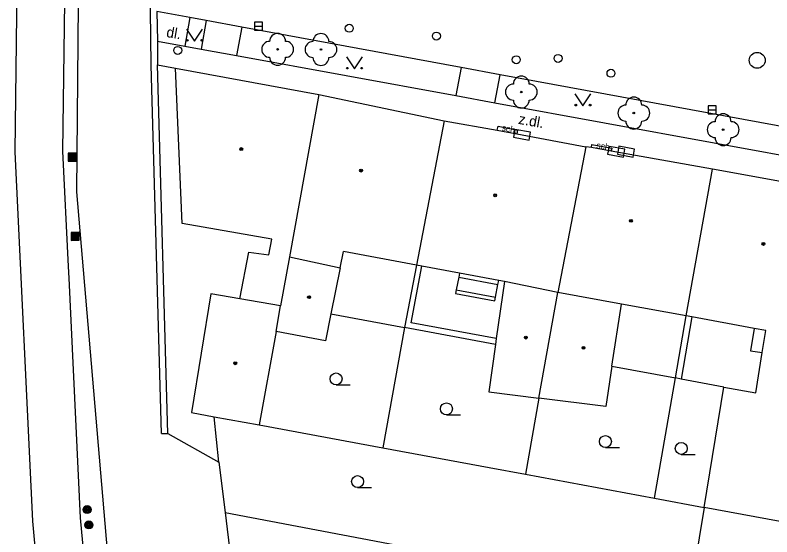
# Model space of a CAD drawing. Extents: x -596229 to -595156, y -1161237 to -1159376.
# Drawn here: x -596138.97 to -596091.46, y -1160439.45 to -1160406.71 of the extents above; entities that cross this region are included whole.
import ezdxf

# ---------------------------------------------------------------- set-up
doc = ezdxf.new("R2010")
doc.units = 0
for name, color, linetype in [('DOP - budovy nerozlisene - VP', 7, 'Continuous'), ('DOP - kresba z DSPS bez souradnic', 7, 'Continuous'), ('DOP - rozhrani ploch obecne', 7, 'Continuous'), ('Level 22', 7, 'Continuous'), ('Level 24', 7, 'Continuous'), ('Level 25', 7, 'Continuous'), ('Level 27', 7, 'Continuous'), ('Level 28', 7, 'Continuous'), ('Level 36', 7, 'Continuous'), ('Level 39', 7, 'Continuous'), ('TM - budovy zdene_ betonove - VP', 7, 'Continuous'), ('TM - CD - osa koleji', 7, 'Continuous'), ('TM - chodniky - VP', 7, 'Continuous'), ('TM - horni hrana svahu', 7, 'Continuous'), ('TM - komunikace - VP', 7, 'Continuous'), ('TM - letecke snimky - pomocna linie', 7, 'Continuous'), ('TM - plot drateny_ kovovy - VP', 7, 'Continuous'), ('TM - plot nerozliseny - VP', 7, 'Continuous'), ('TM - popis povrchu', 7, 'Continuous'), ('TM - poznamka', 7, 'Continuous'), ('TM - rozhrani mezi zpev. plochami mezi sebou - VP', 7, 'Continuous'), ('TM - rozhrani ploch obecne - VP', 7, 'Continuous'), ('TM - schody - VP', 7, 'Continuous'), ('TM - zed operna - VP', 7, 'Continuous')]:
    doc.layers.add(name, color=color, linetype=linetype)

msp = doc.modelspace()

# ---------------------------------------------------------------- linework, layer by layer
at = {"layer": 'DOP - budovy nerozlisene - VP'}
for points in [[(-596126.68, -1160424.21), (-596127.89, -1160431.65)], [(-596124.86, -1160424.52), (-596126.68, -1160424.21)], [(-596122.59, -1160426.57), (-596123.65, -1160432.43)], [(-596127.89, -1160431.65), (-596126.48, -1160431.91)], [(-596126.48, -1160431.91), (-596123.65, -1160432.43)]]:
    msp.add_lwpolyline(points, dxfattribs=at)
at = {"layer": 'DOP - kresba z DSPS bez souradnic'}
for points in [[(-596114.11, -1160426.03), (-596113.43, -1160422.46)], [(-596096.49, -1160425.65), (-596097.15, -1160429.55)], [(-596108.76, -1160427.01), (-596114.11, -1160426.03)]]:
    msp.add_lwpolyline(points, dxfattribs=at)
at = {"layer": 'DOP - rozhrani ploch obecne'}
for points in [[(-596113.77, -1160422.4), (-596114.52, -1160426.31)], [(-596119.15, -1160425.45), (-596114.52, -1160426.31)], [(-596097.5, -1160429.48), (-596096.84, -1160425.58)], [(-596114.52, -1160426.31), (-596115.88, -1160433.87)], [(-596108.81, -1160427.37), (-596114.52, -1160426.31)], [(-596101.5, -1160428.74), (-596097.5, -1160429.48)], [(-596098.83, -1160437.02), (-596097.5, -1160429.48)], [(-596097.15, -1160429.55), (-596097.5, -1160429.48)], [(-596094.47, -1160430.05), (-596097.15, -1160429.55)], [(-596106.1, -1160430.75), (-596106.93, -1160435.52)], [(-596126.19, -1160434.76), (-596126.48, -1160431.91)], [(-596123.65, -1160432.43), (-596115.88, -1160433.87)], [(-596115.88, -1160433.87), (-596109.2, -1160435.1)], [(-596109.2, -1160435.1), (-596106.93, -1160435.52)], [(-596106.93, -1160435.52), (-596098.83, -1160437.02)], [(-596098.83, -1160437.02), (-596095.71, -1160437.6)], [(-596125.79, -1160437.93), (-596096.67, -1160443.44)]]:
    msp.add_lwpolyline(points, dxfattribs=at)
at = {"layer": 'Level 22'}
for centre in [(-596122.49, -1160408.86), (-596119.77, -1160408.87), (-596107.19, -1160411.54), (-596100.13, -1160412.86), (-596094.52, -1160413.9)]:
    msp.add_circle(centre, 0.05, dxfattribs=at)
for centre, start, end in [((-596122.49, -1160408.36), 0, 180), ((-596119.77, -1160408.37), 0, 180), ((-596122.99, -1160408.86), 90, 270), ((-596121.99, -1160408.86), 270, 90), ((-596120.27, -1160408.87), 90, 270), ((-596119.27, -1160408.87), 270, 90), ((-596122.49, -1160409.36), 180, 0), ((-596119.77, -1160409.37), 180, 0), ((-596107.19, -1160411.04), 0, 180), ((-596107.69, -1160411.54), 90, 270), ((-596106.69, -1160411.54), 270, 90), ((-596107.19, -1160412.04), 180, 0), ((-596100.13, -1160412.36), 0, 180), ((-596100.63, -1160412.86), 90, 270), ((-596099.63, -1160412.86), 270, 90), ((-596094.52, -1160413.4), 0, 180), ((-596100.13, -1160413.36), 180, 0), ((-596095.02, -1160413.9), 90, 270), ((-596094.02, -1160413.9), 270, 90), ((-596094.52, -1160414.4), 180, 0)]:
    msp.add_arc(centre, 0.5, start, end, dxfattribs=at)
at = {"layer": 'Level 24'}
for points in [[(-596106.606, -1160414.065), (-596107.589, -1160413.882), (-596107.68, -1160414.374), (-596106.697, -1160414.557)], [(-596100.697, -1160415.132), (-596101.681, -1160414.955), (-596101.769, -1160415.447), (-596100.785, -1160415.624)], [(-596100.076, -1160415.124), (-596101.06, -1160414.944), (-596101.15, -1160415.435), (-596100.166, -1160415.616)]]:
    msp.add_lwpolyline(points, close=True, dxfattribs=at)
at = {"layer": 'Level 25'}
for points in [[(-596135.635, -1160415.885), (-596135.135, -1160415.875), (-596135.145, -1160415.375), (-596135.645, -1160415.385)], [(-596135.586, -1160415.834), (-596135.186, -1160415.826), (-596135.194, -1160415.426), (-596135.594, -1160415.434)], [(-596135.537, -1160415.783), (-596135.237, -1160415.777), (-596135.243, -1160415.477), (-596135.543, -1160415.483)], [(-596135.488, -1160415.732), (-596135.288, -1160415.728), (-596135.292, -1160415.528), (-596135.492, -1160415.532)], [(-596135.439, -1160415.681), (-596135.339, -1160415.679), (-596135.341, -1160415.579), (-596135.441, -1160415.581)], [(-596135.445, -1160420.845), (-596134.945, -1160420.835), (-596134.955, -1160420.335), (-596135.455, -1160420.345)], [(-596135.396, -1160420.794), (-596134.996, -1160420.786), (-596135.004, -1160420.386), (-596135.404, -1160420.394)], [(-596135.347, -1160420.743), (-596135.047, -1160420.737), (-596135.053, -1160420.437), (-596135.353, -1160420.443)], [(-596135.298, -1160420.692), (-596135.098, -1160420.688), (-596135.102, -1160420.488), (-596135.302, -1160420.492)], [(-596135.249, -1160420.641), (-596135.149, -1160420.639), (-596135.151, -1160420.539), (-596135.251, -1160420.541)]]:
    msp.add_lwpolyline(points, close=True, dxfattribs=at)
for centre, radius in [((-596134.45, -1160437.74), 0.25), ((-596134.45, -1160437.74), 0.2), ((-596134.45, -1160437.74), 0.15), ((-596134.45, -1160437.74), 0.1), ((-596134.45, -1160437.74), 0.05), ((-596134.34, -1160438.7), 0.25), ((-596134.34, -1160438.7), 0.2), ((-596134.34, -1160438.7), 0.15), ((-596134.34, -1160438.7), 0.1), ((-596134.34, -1160438.7), 0.05)]:
    msp.add_circle(centre, radius, dxfattribs=at)
at = {"layer": 'Level 27'}
for p, q in [((-596123.94, -1160407.4), (-596123.44, -1160407.4)), ((-596095.46, -1160412.66), (-596094.96, -1160412.66))]:
    msp.add_line(p, q, dxfattribs=at)
for points in [[(-596123.94, -1160407.65), (-596123.44, -1160407.65), (-596123.44, -1160407.15), (-596123.94, -1160407.15)], [(-596095.46, -1160412.91), (-596094.96, -1160412.91), (-596094.96, -1160412.41), (-596095.46, -1160412.41)]]:
    msp.add_lwpolyline(points, close=True, dxfattribs=at)
msp.add_circle((-596092.38, -1160409.55), 0.5, dxfattribs=at)
at = {"layer": 'Level 28'}
for centre in [(-596117.99, -1160407.54), (-596112.52, -1160408.03), (-596128.76, -1160408.93), (-596107.51, -1160409.51), (-596104.88, -1160409.43), (-596101.56, -1160410.36)]:
    msp.add_circle(centre, 0.25, dxfattribs=at)
at = {"layer": 'Level 36'}
for p, q in [((-596118.82, -1160429.915), (-596117.945, -1160429.915)), ((-596111.89, -1160431.795), (-596111.015, -1160431.795)), ((-596101.91, -1160433.845), (-596101.035, -1160433.845)), ((-596097.15, -1160434.275), (-596096.275, -1160434.275)), ((-596117.47, -1160436.355), (-596116.595, -1160436.355))]:
    msp.add_line(p, q, dxfattribs=at)
for points in [[(-596128.21, -1160407.59), (-596127.71, -1160408.34), (-596127.21, -1160407.59)], [(-596118.16, -1160409.34), (-596117.66, -1160410.09), (-596117.16, -1160409.34)], [(-596103.82, -1160411.66), (-596103.32, -1160412.41), (-596102.82, -1160411.66)]]:
    msp.add_lwpolyline(points, dxfattribs=at)
for centre, radius in [((-596128.16, -1160408.29), 0.05), ((-596127.261, -1160408.29), 0.05), ((-596118.11, -1160410.04), 0.05), ((-596117.211, -1160410.04), 0.05), ((-596103.77, -1160412.36), 0.05), ((-596102.871, -1160412.36), 0.05), ((-596118.82, -1160429.54), 0.375), ((-596111.89, -1160431.42), 0.375), ((-596101.91, -1160433.47), 0.375), ((-596097.15, -1160433.9), 0.375), ((-596117.47, -1160435.98), 0.375)]:
    msp.add_circle(centre, radius, dxfattribs=at)
at = {"layer": 'Level 39'}
for centre, radius in [((-596124.77, -1160415.12), 0.09), ((-596124.77, -1160415.12), 0.0398), ((-596117.25, -1160416.47), 0.09), ((-596117.25, -1160416.47), 0.0398), ((-596108.83, -1160418.02), 0.09), ((-596108.83, -1160418.02), 0.0398), ((-596100.31, -1160419.62), 0.09), ((-596100.31, -1160419.62), 0.0398), ((-596091.99, -1160421.07), 0.09), ((-596091.99, -1160421.07), 0.0398), ((-596120.52, -1160424.41), 0.09), ((-596120.52, -1160424.41), 0.0398), ((-596106.91, -1160426.95), 0.09), ((-596106.91, -1160426.95), 0.0398), ((-596103.29, -1160427.59), 0.09), ((-596103.29, -1160427.59), 0.0398), ((-596125.15, -1160428.56), 0.09), ((-596125.15, -1160428.56), 0.0398)]:
    msp.add_circle(centre, radius, dxfattribs=at)
at = {"layer": 'TM - budovy zdene_ betonove - VP'}
for points in [[(-596128.48, -1160419.79), (-596128.91, -1160410.05)], [(-596128.91, -1160410.05), (-596119.9, -1160411.7)], [(-596119.9, -1160411.7), (-596121.74, -1160421.87)], [(-596119.9, -1160411.7), (-596112.03, -1160413.34)], [(-596112.03, -1160413.34), (-596113.77, -1160422.4)], [(-596112.03, -1160413.34), (-596108.7, -1160413.94)], [(-596108.7, -1160413.94), (-596107.48, -1160414.16)], [(-596107.48, -1160414.16), (-596103.13, -1160414.97)], [(-596103.13, -1160414.97), (-596104.9, -1160424.11)], [(-596102.79, -1160415.03), (-596103.13, -1160414.97)], [(-596101.54, -1160415.25), (-596102.79, -1160415.03)], [(-596095.19, -1160416.38), (-596101.54, -1160415.25)], [(-596096.84, -1160425.58), (-596095.19, -1160416.38)], [(-596087.23, -1160417.82), (-596095.19, -1160416.38)], [(-596122.86, -1160420.77), (-596128.48, -1160419.79)], [(-596123.05, -1160421.75), (-596122.86, -1160420.77)], [(-596124.86, -1160424.52), (-596124.3, -1160421.58)], [(-596124.3, -1160421.58), (-596123.05, -1160421.75)], [(-596118.57, -1160422.57), (-596118.36, -1160421.54)], [(-596113.77, -1160422.4), (-596118.36, -1160421.54)], [(-596121.74, -1160421.87), (-596122.3, -1160424.96)], [(-596121.74, -1160421.87), (-596118.57, -1160422.57)], [(-596118.57, -1160422.57), (-596119.15, -1160425.45)], [(-596113.43, -1160422.46), (-596113.77, -1160422.4)], [(-596111.08, -1160422.9), (-596113.43, -1160422.46)], [(-596108.61, -1160423.36), (-596111.08, -1160422.9)], [(-596108.24, -1160423.43), (-596108.76, -1160427.01)], [(-596108.24, -1160423.43), (-596108.61, -1160423.36)], [(-596104.9, -1160424.11), (-596108.24, -1160423.43)], [(-596122.3, -1160424.96), (-596124.86, -1160424.52)], [(-596106.1, -1160430.75), (-596104.9, -1160424.11)], [(-596100.91, -1160424.84), (-596104.9, -1160424.11)], [(-596122.59, -1160426.57), (-596122.3, -1160424.96)], [(-596101.5, -1160428.74), (-596100.91, -1160424.84)], [(-596096.84, -1160425.58), (-596100.91, -1160424.84)], [(-596119.15, -1160425.45), (-596119.49, -1160427.14)], [(-596096.49, -1160425.65), (-596096.84, -1160425.58)], [(-596092.57, -1160426.37), (-596096.49, -1160425.65)], [(-596091.83, -1160426.5), (-596092.57, -1160426.37)], [(-596119.49, -1160427.14), (-596122.59, -1160426.57)], [(-596092.06, -1160427.89), (-596091.83, -1160426.5)], [(-596108.81, -1160427.37), (-596109.24, -1160430.35)], [(-596108.76, -1160427.01), (-596108.81, -1160427.37)], [(-596092.47, -1160430.42), (-596092.06, -1160427.89)], [(-596101.5, -1160428.74), (-596101.89, -1160431.28)], [(-596095.71, -1160437.6), (-596094.47, -1160430.05)], [(-596094.47, -1160430.05), (-596092.47, -1160430.42)], [(-596109.24, -1160430.35), (-596106.1, -1160430.75)], [(-596101.89, -1160431.28), (-596106.1, -1160430.75)], [(-596090.93, -1160438.48), (-596095.71, -1160437.6)]]:
    msp.add_lwpolyline(points, dxfattribs=at)
at = {"layer": 'TM - CD - osa koleji'}
msp.add_lwpolyline([(-596070.84, -1160662.58), (-596079.19, -1160639.25), (-596089.53, -1160610.33), (-596100.36, -1160580), (-596108.92, -1160555.81), (-596119.29, -1160525.88), (-596123.37, -1160513.21), (-596128.62, -1160494.53), (-596133.1, -1160473.96), (-596137.29, -1160444.66), (-596137.85, -1160438.46), (-596138.97, -1160415.3), (-596138.73, -1160396.35), (-596137.86, -1160382.04), (-596135.04, -1160357.75), (-596130.33, -1160332.57), (-596130.02, -1160331.12), (-596125.76, -1160311.5)], dxfattribs=at)
at = {"layer": 'TM - chodniky - VP'}
for points in [[(-596128, -1160406.87), (-596128.31, -1160408.66)], [(-596126.97, -1160407.06), (-596127.29, -1160408.85)], [(-596124.74, -1160407.47), (-596125.07, -1160409.25)], [(-596128.31, -1160408.66), (-596127.29, -1160408.85)], [(-596125.07, -1160409.25), (-596111.3, -1160411.76)], [(-596110.97, -1160410), (-596111.3, -1160411.76)], [(-596108.85, -1160412.21), (-596108.52, -1160410.45)], [(-596108.85, -1160412.21), (-596088.2, -1160415.98)]]:
    msp.add_lwpolyline(points, dxfattribs=at)
at = {"layer": 'TM - horni hrana svahu'}
msp.add_lwpolyline([(-596068.78, -1160660.14), (-596070.7, -1160650.38), (-596075.5, -1160636.41), (-596084.94, -1160608.71), (-596096.48, -1160580.01), (-596099.31, -1160572.83), (-596115.34, -1160526.77), (-596124.43, -1160494.43), (-596128.99, -1160469.32), (-596133.17, -1160440.33), (-596135.09, -1160417.8), (-596134.81, -1160384.75)], dxfattribs=at)
at = {"layer": 'TM - komunikace - VP'}
for points in [[(-596128, -1160406.87), (-596130.07, -1160406.49)], [(-596126.97, -1160407.06), (-596128, -1160406.87)], [(-596124.74, -1160407.47), (-596126.97, -1160407.06)], [(-596110.97, -1160410), (-596124.74, -1160407.47)], [(-596108.52, -1160410.45), (-596110.97, -1160410)], [(-596087.89, -1160414.25), (-596108.52, -1160410.45)]]:
    msp.add_lwpolyline(points, dxfattribs=at)
at = {"layer": 'TM - letecke snimky - pomocna linie'}
for points in [[(-596115.45, -1160527.8), (-596116.44, -1160524.93), (-596120.5, -1160512.34), (-596125.71, -1160493.8), (-596129.06, -1160478.39), (-596129.71, -1160475.42), (-596130.15, -1160473.43), (-596134.31, -1160444.31), (-596134.86, -1160438.25), (-596135.58, -1160423.21), (-596135.62, -1160422.49), (-596135.97, -1160415.25), (-596135.73, -1160396.46), (-596134.81, -1160384.75)], [(-596129.79, -1160432.97), (-596129.39, -1160432.96)], [(-596095.71, -1160437.6), (-596096.67, -1160443.44)]]:
    msp.add_lwpolyline(points, dxfattribs=at)
at = {"layer": 'TM - plot drateny_ kovovy - VP'}
for points in [[(-596129.39, -1160432.96), (-596130.03, -1160409.84)], [(-596130.03, -1160409.84), (-596128.91, -1160410.05)]]:
    msp.add_lwpolyline(points, dxfattribs=at)
at = {"layer": 'TM - plot nerozliseny - VP'}
for points in [[(-596129.39, -1160432.96), (-596126.19, -1160434.76)], [(-596126.19, -1160434.76), (-596125.79, -1160437.93)], [(-596125.79, -1160437.93), (-596124.9, -1160445.21)]]:
    msp.add_lwpolyline(points, dxfattribs=at)
at = {"layer": 'TM - rozhrani mezi zpev. plochami mezi sebou - VP'}
for points in [[(-596130.03, -1160408.35), (-596128.31, -1160408.66)], [(-596127.29, -1160408.85), (-596125.07, -1160409.25)], [(-596111.3, -1160411.76), (-596108.85, -1160412.21)]]:
    msp.add_lwpolyline(points, dxfattribs=at)
at = {"layer": 'TM - rozhrani ploch obecne - VP'}
for points in [[(-596130.07, -1160406.49), (-596130.03, -1160408.35)], [(-596130.03, -1160408.35), (-596130.03, -1160409.84)], [(-596108.7, -1160413.94), (-596108.65, -1160413.69), (-596107.44, -1160413.93), (-596107.48, -1160414.16)], [(-596102.79, -1160415.03), (-596102.76, -1160414.84), (-596101.5, -1160415.07), (-596101.54, -1160415.25)], [(-596111.08, -1160422.9), (-596111.12, -1160423.15)], [(-596111.12, -1160423.15), (-596111.28, -1160423.94)], [(-596111.12, -1160423.15), (-596108.66, -1160423.61)], [(-596108.66, -1160423.61), (-596108.61, -1160423.36)], [(-596111.28, -1160423.94), (-596111.32, -1160424.18), (-596108.85, -1160424.64), (-596108.82, -1160424.4)], [(-596111.28, -1160423.94), (-596108.82, -1160424.4)], [(-596108.82, -1160424.4), (-596108.66, -1160423.61)], [(-596092.57, -1160426.37), (-596092.8, -1160427.77), (-596092.06, -1160427.89)]]:
    msp.add_lwpolyline(points, dxfattribs=at)
at = {"layer": 'TM - schody - VP'}
for points in [[(-596108.7, -1160413.94), (-596108.65, -1160413.69), (-596107.44, -1160413.93), (-596107.48, -1160414.16)], [(-596102.79, -1160415.03), (-596102.76, -1160414.84), (-596101.5, -1160415.07), (-596101.54, -1160415.25)]]:
    msp.add_lwpolyline(points, dxfattribs=at)
at = {"layer": 'TM - zed operna - VP'}
for points in [[(-596130.43, -1160409.85), (-596130.61, -1160394.31)], [(-596129.79, -1160432.97), (-596130.43, -1160409.85)]]:
    msp.add_lwpolyline(points, dxfattribs=at)

# ---------------------------------------------------------------- texts
at = {"layer": 'TM - popis povrchu'}
for s, rotation, p in [('dl.', 350.488, (-596129.51, -1160408.08)), ('z.dl.', 349.9036, (-596107.41, -1160413.53))]:
    msp.add_text(s, height=0.65, rotation=rotation, dxfattribs=at).set_placement(p)
at = {"layer": 'TM - poznamka'}
for rotation, p in [(349, (-596108.44, -1160413.96)), (349.6551, (-596102.5, -1160415.06))]:
    msp.add_text('sch.', height=0.4, rotation=rotation, dxfattribs=at).set_placement(p)

doc.saveas('drawing.dxf')
